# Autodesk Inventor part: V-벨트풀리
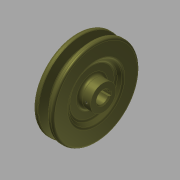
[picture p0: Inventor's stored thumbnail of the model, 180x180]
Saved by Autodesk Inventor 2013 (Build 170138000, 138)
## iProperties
Company: 한국ATC센터
Created: 2015-12
Part Number: V-벨트풀리
Document SubType Name: Modeling
Designer: mdu
Density: 7.25 g/cm^3
Mass: 594.58 g
Surface Area: 210.471 cm^2
Volume: 82.011 cm^3
Material: 주철
Author: mdu
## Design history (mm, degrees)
sketch "스케치1"
  geometry: L1 (-13, 0)-(13, 0); L2 (-13, 0)-(-13, 12.5); L3 (-13, 12.5)-(-9, 12.5); L4 (-9, 12.5)-(-9, 23); L5 (-9, 23)-(-13, 27); L6 (-13, 27)-(-13, 42.7); L7 (-13, 42.7)-(-8.325, 42.7); L8 (-8.325, 42.7)-(-5.574, 33.7); L9 (-5.574, 33.7)-(-1.426, 33.7); L10 (-1.426, 33.7)-(1.325, 42.7); L11 (1.325, 42.7)-(6, 42.7); L12 (6, 42.7)-(6, 27); L13 (6, 27)-(2, 23); L14 (2, 23)-(2, 12.5); L15 (2, 12.5)-(13, 12.5); L16 (13, 12.5)-(13, 0); L17 (-7.5, 40)-(0.5, 40); 2 further points
  constraints: 34 end point, 6 parallel, 5 collinear, 5 equal length, 4 perpendicular, 2 point on line, 1 coincident, 1 horizontal, 1 midpoint
  dimensions: "d0" = 26 distance of L1.start L1.end; "d1" = 2.7 distance between parallel lines of L7 L17; "d2" = 6.3 distance between parallel lines of L9 L17; "d3" = 8 distance of L17.start L17.end; "d4" = 34 deg angle of L10 L8; "d5" = 19 distance between parallel lines of L12 L6; "d7" = 25 diameter of L15 L1; "d8" = 46 diameter of L13.end L1; "d9" = 54 diameter of L12.end L1; "d10" = 4 distance between parallel lines of L2 L4; "d11" = 80 diameter of L17 L1
revolve "회전1" sketch "스케치1" stored, may be unused: angle "d12" = 90 deg
sketch "스케치2"
  geometry: L1 (-2, 5.657)-(-2, 7.8); L2 (-2, 7.8)-(2, 7.8); L3 (2, 7.8)-(2, 5.657); A1 r 6 centre (0, 0) between (-2, 5.657) and (2, 5.657); 1 further point
  constraints: 6 end point, 2 parallel, 2 point on circle, 1 centre point, 1 coincident, 1 perpendicular, 1 vertical
  dimensions: "d13" = 12 diameter of A1; "d14" = 13.8 dimension on A1 L2; "d15" = 4 distance of L1.end L2.end
extrude "돌출1" cut sketch "스케치2" stored distance "d16" = 10; taper "d17" = 0 deg
node "작업 평면1"
sketch "스케치3"
  geometry: L1 (-5.5, 12.5)-(-5.5, -12.5) reference; L2 (20.5, 27)-(20.5, -27) reference; 3 further points
  constraints: 1 horizontal alignment, 1 midpoint
  dimensions: "d18" = 4 distance from line of point (-1.5, 0) L1; "d33" = 22 distance from line of point (-1.5, 0) L2 (derived)
hole "구멍1" sketch "스케치3" at (-1.5, 0) diameter "d19" = 2.459; stored, may be unused: countersink angle "d23" = 90 deg, drill point angle "d25" = 118 deg; dims "d20" = 6, "d21" = 4, "d22" = 2, "d24" = 8
fillet "모깎기1" dims "d26" = 2, "d27" = 0.5, "d28" = 1, "d29" = 3
chamfer "모따기1" distance "d30" = 1; stored, may be unused: second distance "d31" = 2, angle "d32" = 45 deg
node "솔리드1"
